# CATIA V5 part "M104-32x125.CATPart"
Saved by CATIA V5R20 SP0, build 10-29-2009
Part number: M104-32x125
Source: Unknown
Bounding box of the stored display mesh (mm): x -15.868 to 15.868, y -15.868 to 15.868, z 0 to 125
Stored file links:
  C:\Users\Utente\Desktop\IO LAVORO\3D X SITO CF\X SITO\M104\M104-32x125.CATPart

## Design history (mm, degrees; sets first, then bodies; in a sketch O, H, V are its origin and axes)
Body1 (main body)
  Solid1 "PartBody": solid without history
